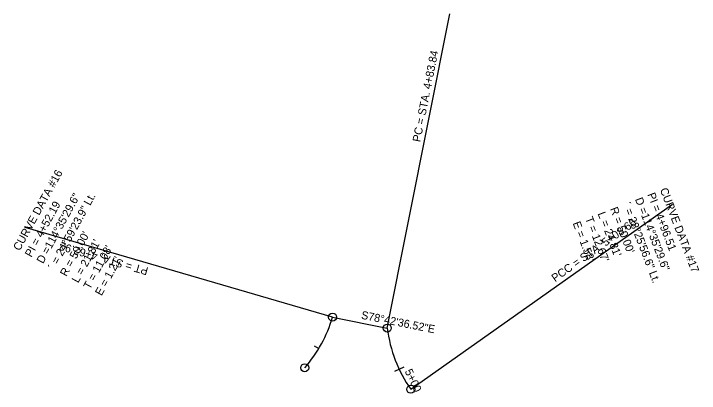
# Model space of a CAD drawing. Extents: x 1158784 to 1165006, y 610007 to 611539.
# Drawn here: x 1159880.4 to 1160137.3, y 611149.9 to 611292 of the extents above; entities that cross this region are included whole.
import ezdxf

# ---------------------------------------------------------------- set-up
doc = ezdxf.new("R2010")
doc.units = 0
for name, color, linetype in [('D_Roadway_Centerline', 7, 'Continuous'), ('D_Roadway_Centerline_Bearings', 7, 'Continuous'), ('D_Roadway_Centerline_CurveData', 7, 'Continuous'), ('D_Roadway_Centerline_Flags', 7, 'Continuous'), ('D_Roadway_Centerline_Text', 7, 'Continuous')]:
    doc.layers.add(name, color=color, linetype=linetype)

msp = doc.modelspace()

# ---------------------------------------------------------------- linework, layer by layer
at = {"layer": 'D_Roadway_Centerline'}
msp.add_line((1159999.89, 611178.38), (1160020.41, 611174.29), dxfattribs=at)
for centre, start, end in [((1159951.89, 611192.37), 318.7585, 343.7485), ((1160070.06, 611180.22), 186.8213, 215.2537)]:
    msp.add_arc(centre, 50, start, end, dxfattribs=at)
at = {"layer": 'D_Roadway_Centerline_Flags'}
for points in [[(1160020.41, 611174.29), (1160043.9, 611291.96)], [(1160029.23, 611151.36), (1160127.22, 611220.63)], [(1159999.89, 611178.38), (1159884.68, 611211.96)]]:
    msp.add_lwpolyline(points, dxfattribs=at)
for centre in [(1159999.89, 611178.38), (1160020.41, 611174.29), (1159989.48, 611159.41), (1160029.23, 611151.36)]:
    msp.add_circle(centre, 1.5, dxfattribs=at)
at = {"layer": 'D_Roadway_Centerline_Text'}
for points in [[(1159993.01, 611167.62), (1159994.72, 611166.58)], [(1160026.67, 611159.68), (1160023.06, 611157.97)]]:
    msp.add_lwpolyline(points, dxfattribs=at)

# ---------------------------------------------------------------- texts
at = {"layer": 'D_Roadway_Centerline_Bearings'}
msp.add_text('S78%%d42\'36.52"E', height=3, rotation=348.7101, dxfattribs=at).set_placement((1160010.44, 611177.8))
at = {"layer": 'D_Roadway_Centerline_CurveData'}
for s, rotation, p in [('CURVE DATA #16', 61.2535, (1159882.67, 611202.97)), ('CURVE DATA #17', 291.0375, (1160122.5, 611226.11)), ('D =114%%d35\'29.6"', 61.2535, (1159891.43, 611198.16)), ('´ = 24%%d59\'23.9" Lt.', 61.2535, (1159895.82, 611195.76)), ('PI = 4+96.51', 291.0375, (1160117.83, 611224.31)), ('PI = 4+52.19', 61.2535, (1159887.05, 611200.57)), ('´ = 28%%d25\'56.6" Lt.', 291.0375, (1160108.5, 611220.72)), ('D =114%%d35\'29.6"', 291.0375, (1160113.17, 611222.52)), ("R = 50.00'", 291.0375, (1160103.83, 611218.93)), ("T = 12.67'", 291.0375, (1160094.5, 611215.34)), ("L = 24.81'", 291.0375, (1160099.17, 611217.13)), ("E = 1.58'", 291.0375, (1160089.83, 611213.54)), ("R = 50.00'", 61.2535, (1159900.2, 611193.35)), ("L = 21.81'", 61.2535, (1159904.58, 611190.95)), ("T = 11.08'", 61.2535, (1159908.97, 611188.54)), ("E = 1.21'", 61.2535, (1159913.35, 611186.14))]:
    msp.add_text(s, height=3, rotation=rotation, dxfattribs=at).set_placement(p)
at = {"layer": 'D_Roadway_Centerline_Flags'}
for s, rotation, p in [('PC = STA. 4+83.84', 78.7101, (1160032.75, 611243.75)), ('PCC = STA. 5+08.66', 35.2537, (1160083.28, 611191.4)), ('PT = STA. 4+62.92', 163.7485, (1159931.08, 611196.88))]:
    msp.add_text(s, height=3, rotation=rotation, dxfattribs=at).set_placement(p)
at = {"layer": 'D_Roadway_Centerline_Text'}
msp.add_text('5+00', height=3, rotation=295.3357, dxfattribs=at).set_placement((1160026.86, 611158.11))

doc.saveas('drawing.dxf')
